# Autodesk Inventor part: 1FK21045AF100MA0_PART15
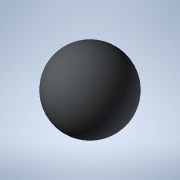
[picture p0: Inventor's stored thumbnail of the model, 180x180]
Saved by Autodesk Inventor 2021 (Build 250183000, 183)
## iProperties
Created: 2025-04
Part Number: 1FK21045AF100MA0_PART15
Material: Generic
Catalog Web Link: www.3dfindit.com
Description: -Servo synchronous motor
Document SubType Name: Modeling
Designer: psAdmin
Mass: 0.137258 g
Surface Area: 1.2868 cm^2
Volume: 0.137258 cm^3
Density: 1 g/cm^3
Appearance: PSOLRGB-212-217-219
Category: PARTsolutions
Title: 1FK21045AF100MA0_PART15
Author: Cadenas PARTsolutions
Comments: Servo synchronous motor
Sending System: PARTsolutions
Preprocessor: ST-DEVELOPER v19.3
PSOL_IDENT_0: {$CADENAS_DATA/23d-libs/siemens_ag/_cat_/52/6b/1fk21045af100ma0.prj},216 {VTYP=3D},{NB=1FK21045AF100
PSOL_IDENT_1: MA0_PART15},{LINA=1FK21045AF100MA0_PART15},{NN=1FK21045AF100MA0_PART15},{NOPRJ=TRUE},{DATE=19.08.202
PSOL_IDENT_2: 5 14:00:38},{GEOMDATE=30.07.2025 02:01:45},{VERSION=},{LINEID=10},{WBVAR=},{WBNUMERIC=}  {NB=1FK2104
PSOL_IDENT_3: 5AF100MA0_PART15},{LINA=1FK21045AF100MA0_PART15},{KT=DUMMY},{PREVIEW=../../../_pool_/cb/72/p_d211_xx
PSOL_IDENT_4: _00434j.png},{DESCSHORT=SIMOTICS S-1FK2 HD, SINAMICS S210 3AC 400V-480V, 2.4 Nm, 3000 rpm},{DESCLONG=
PSOL_IDENT_5: SIMOTICS S-1FK2 HD servo motor M0=2.4 Nm; PN = 0.75 kW at nN=3000 rpm (380-480 V); PN = 0.375 kW at
PSOL_IDENT_6: nN=1500 rpm (200-240 V); with holding brake; degree of protection IP64; cylindrical shaft D19x40mm;
PSOL_IDENT_7: absolute encoder 22-bit + 12-bit multiturn (encoder AM22DQC); with OCC interface; plug size M17, rot
PSOL_IDENT_8: atable; SIMOTICS S-1FK2 servomotorfor a wide range of uses in industrial environments. SIMOTICS S‑1F
PSOL_IDENT_9: K2 servomotors are compact synchronous motors with a high dynamic performance that set themselves ap
PSOL_IDENT_10: art as a result of their high power density, degree of protection and overload capability. The motor
PSOL_IDENT_11: s are available in two variants: as High Dynamic variant (highest dynamic performance as a result of
PSOL_IDENT_12: the low intrinsic moment of inertia for applications demanding a high dynamic performance with low
PSOL_IDENT_13: moved masses) - and as Compact variant (precise and stable closed-loop control for medium up to larg
PSOL_IDENT_14: e moved masses as a result of a medium intrinsic moment of inertia). SIMOTICSS‑1FK2 servomotors full
PSOL_IDENT_15: y exploit their strengths in a system with the SINAMICSS210 frequency converter and simple connectio
PSOL_IDENT_16: n using the one cable connection (OCC). Advantages include the short control and positioning times,
PSOL_IDENT_17: fast and precise correction of disturbing quantities as well as stable control with a high dynamic p
PSOL_IDENT_18: erformance. The servo motors can be configured to address a wide range of requirements. For example
PSOL_IDENT_19: with and without holding brake, IP64 or IP65 degree of protection, singleturn or multiturn absolute
PSOL_IDENT_20: encoders - to name just a few. Further, the servomotors are available in different shaft heights ext
PSOL_IDENT_21: ending from 20 to 100. A shaft sealing ring is available to achieve an IP65 degree of protection and
PSOL_IDENT_22: for subsequent mounting at the motor or as spare part. SIMOTICS - the optimum motor for each and ev
PSOL_IDENT_23: ery motion control application.},{INTNO=804766906411},{SUPPLIERALTNO=1FK2104-5AF10-0MA0},{MANUID=1FK
PSOL_IDENT_24: 21045AF100MA0},{MANUNAME=Siemens},{MANUTYPEDESC=Synchronous motor 1FK2-HD 2.4 NM},{AAU732=SIMOTICS},
PSOL_IDENT_25: {AAO057=S-1FK2},{AAU734=SIMOTICS S-1FK2 HD servo motor M0=2.4 Nm; PN = 0.75 kW at nN=3000 rpm (380-4
PSOL_IDENT_26: 80 V); PN = 0.375 kW at nN=1500 rpm (200-240 V); with holding brake; degree of protection IP64; cyli
PSOL_IDENT_27: ndrical shaft D19x40mm; absolute encoder 22-bit + 12-bit multiturn (encoder AM22DQC); with OCC inter
PSOL_IDENT_28: face; plug size M17, rotatable;},{AAW338=Synchronous motor 1FK2-HD 2.4 NM},{AAO742=SIMOTICS},{AAO663=
PSOL_IDENT_29: 4042948693070},{NOCUPEROU=1},{PRICEQUANTITY=1},{QUANTITYMIN=1},{QUANTITYINT=1},{CTN=85015100},{COO=D
PSOL_IDENT_30: E},{AAO676=1FK2104-5AF10-0MA0},{AAO677=Siemens AG},{ORDERUNIT=C62},{CONTENTUNIT=C62}
NB: 1FK21045AF100MA0_PART15
NT: Servo synchronous motor
NBSYN: $MANUID._PART15
LINA: 1FK21045AF100MA0_PART15
CATALOG: SIEMENS
PREVIEW: ../../../_pool_/cb/72/p_d211_xx_00434j.png
DESCSHORT: SIMOTICS S-1FK2 HD, SINAMICS S210 3AC 400V-480V, 2.4 Nm, 3000 rpm
DESCLONG: SIMOTICS S-1FK2 HD servo motor M0=2.4 Nm; PN = 0.75 kW at nN=3000 rpm (380-480 V); PN = 0.375 kW at nN=1500 rpm (200-240 V); with holding brake; degree of prote
INTNO: 804766906411
SUPPLIERALTNO: 1FK2104-5AF10-0MA0
MANUID: 1FK21045AF100MA0
MANUNAME: Siemens
MANUTYPEDESC: Synchronous motor 1FK2-HD 2.4 NM
AAU732: SIMOTICS
AAO057: S-1FK2
AAU734: SIMOTICS S-1FK2 HD servo motor M0=2.4 Nm; PN = 0.75 kW at nN=3000 rpm (380-480 V); PN = 0.375 kW at nN=1500 rpm (200-240 V); with holding brake; degree of prote
AAW338: Synchronous motor 1FK2-HD 2.4 NM
AAO742: SIMOTICS
AAO663: 4042948693070.0
NOCUPEROU: 1
PRICEQUANTITY: 1
QUANTITYMIN: 1
QUANTITYINT: 1
CTN: 85015100
COO: DE
ARTICLENO: 1FK21045AF100MA0_PART15
BOMINFO: 1FK21045AF100MA0_PART15
CREATOR: CADENAS GmbH
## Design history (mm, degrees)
feature "2025_04_17_15_34_52_0317"
body "Solid1"
